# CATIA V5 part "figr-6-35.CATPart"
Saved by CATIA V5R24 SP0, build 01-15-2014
Part number: Part1
Bounding box of the stored display mesh (mm): x -40.3 to 40.3, y -45.975 to 45.975, z 0 to 40
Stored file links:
  D:\KAVITA\CATIA V5-6R2014 Project_ Kavita\CATIA V5-6R2014_partfiles\Partfiles\c06_catia_v5-6r2014_prt\figr-6-35.CATPart
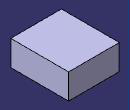
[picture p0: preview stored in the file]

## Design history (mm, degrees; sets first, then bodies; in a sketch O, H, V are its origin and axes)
Body1 (main body)
  Sketch1 on xy-plane, origin (0, 0, 0), H (1, 0, 0), V (0, 1, 0)
    line L1 (-40.2998, 45.9753) -> (40.2998, 45.9753)
    line L2 (40.2998, 45.9753) -> (40.2998, -45.9753)
    line L3 (40.2998, -45.9753) -> (-40.2998, -45.9753)
    line L4 (-40.2998, -45.9753) -> (-40.2998, 45.9753)
    axis line L5 (40.2998, -45.9753) -> (-40.2998, 45.9753)
    horizontal: L1 H, L3 H
    vertical: L2 V, L4 V
    midpoint: O L5
  Pad1: profile Sketch1, direction (0, 0, 1), length 40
